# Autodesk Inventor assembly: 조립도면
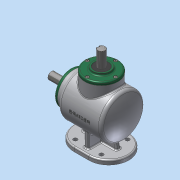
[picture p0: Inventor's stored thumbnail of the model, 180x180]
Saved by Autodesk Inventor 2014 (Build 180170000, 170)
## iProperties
Created: 2023-01
Part Number: 조립도면
Document SubType Name: Assembly
Designer: dg
Author: dg
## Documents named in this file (14)
- C:\Users\dg\Desktop\730106V1021\조립도면.iam
- C:\Users\dg\Desktop\730106V1021\M4.ipt
- C:\Users\dg\Desktop\730106V1021\메인 베벨기어.ipt
- C:\Users\dg\Desktop\730106V1021\메인 축.ipt
- 메인 축.ipt
- C:\Users\dg\Desktop\730106V1021\베어링 6203.ipt
- C:\Users\dg\Desktop\730106V1021\본체.ipt
- C:\Users\dg\Desktop\730106V1021\서브 베벨기어.ipt
- C:\Users\dg\Desktop\730106V1021\서브 축.ipt
- 서브 축.ipt
- C:\Users\dg\Desktop\730106V1021\오일실 17 32 8.ipt
- C:\Users\dg\Desktop\730106V1021\커버.ipt
- C:\Users\dg\Desktop\730106V1021\키 4x4.ipt
- C:\Users\dg\Desktop\730106V1021\키 5x5.ipt
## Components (8 placed, 1 different names)
1. M4:1
2. M4:3
3. M4:4
4. M4:5
5. M4:2
6. M4:6
7. M4:7
8. M4:8
